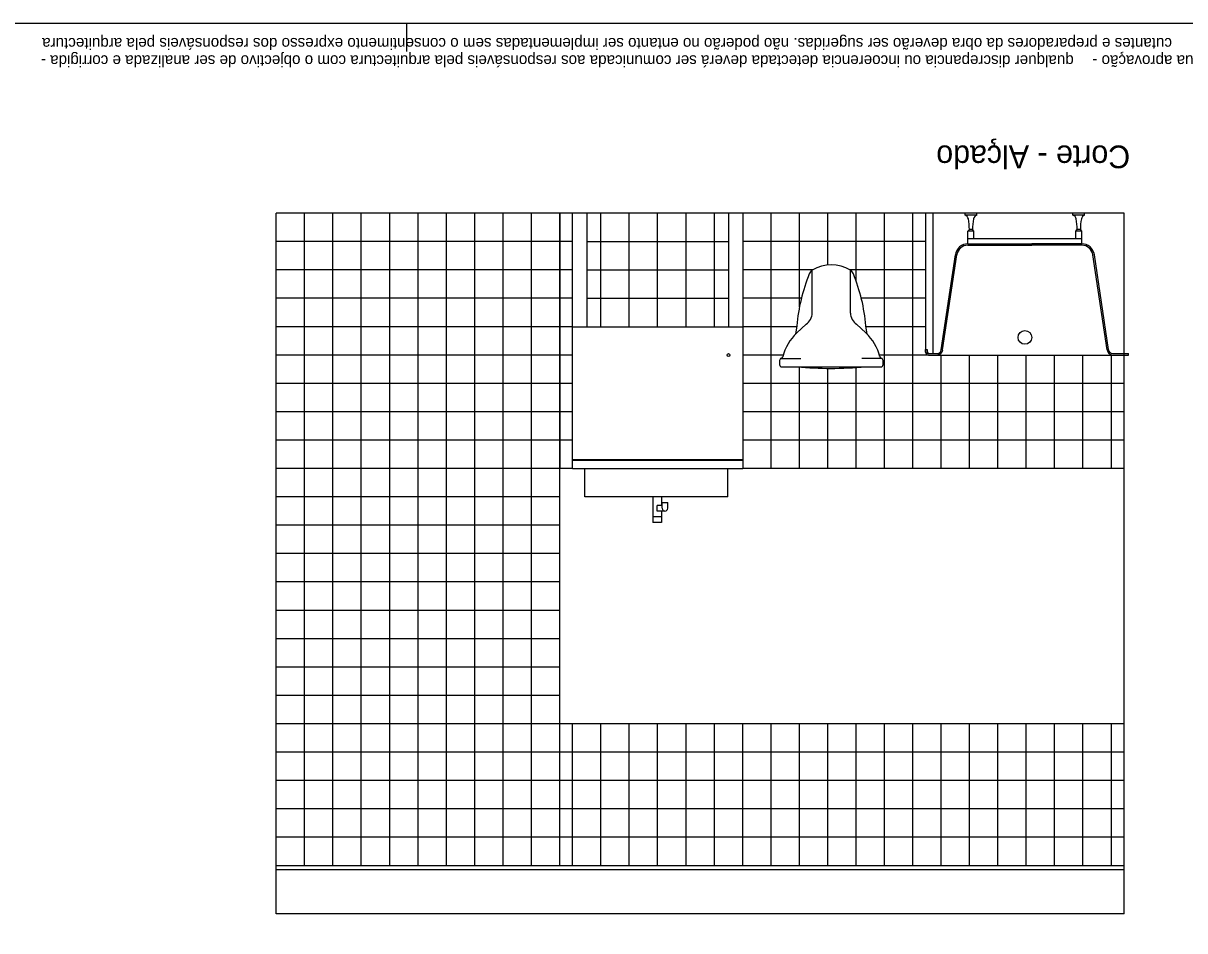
# Model space of a CAD drawing. Extents: x 1302 to 1313.6, y -284.7 to -278.8.
# Drawn here: x 1304.384 to 1308.48, y -281.971 to -278.772 of the extents above; entities that cross this region are included whole.
import ezdxf

# ---------------------------------------------------------------- set-up
doc = ezdxf.new("R2010")
doc.units = 0
for name, color, linetype in [('Level 1', 7, 'Continuous'), ('Level 10', 7, 'Continuous'), ('Level 11', 7, 'Continuous'), ('Level 13', 7, 'Continuous'), ('Level 2', 7, 'Continuous'), ('Level 60', 7, 'Continuous'), ('Level 62', 7, 'Continuous')]:
    doc.layers.add(name, color=color, linetype=linetype)

msp = doc.modelspace()

# ---------------------------------------------------------------- linework, layer by layer
at = {"layer": 'Level 1'}
for p, q in [((1305.2759, -281.9114), (1305.2759, -279.4414)), ((1308.2659, -279.4414), (1305.2759, -279.4414)), ((1307.5659, -279.4414), (1307.5659, -279.9214)), ((1307.5909, -279.4414), (1307.5909, -279.9364)), ((1308.2659, -281.9114), (1308.2659, -279.4414)), ((1307.5659, -279.9214), (1307.5709, -279.9214)), ((1307.5709, -279.9214), (1307.5709, -279.9264)), ((1307.5809, -279.9364), (1307.5909, -279.9364)), ((1308.2659, -281.7414), (1305.2759, -281.7414)), ((1308.2659, -281.7564), (1305.2759, -281.7564)), ((1308.2659, -281.9114), (1305.2759, -281.9114))]:
    msp.add_line(p, q, dxfattribs=at)
msp.add_arc((1307.5809, -279.9264), 0.01, 180, 270, dxfattribs=at)
at = {"layer": 'Level 10'}
for p, q in [((1305.3759, -281.7414), (1305.3759, -279.4414)), ((1305.4759, -281.7414), (1305.4759, -279.4414)), ((1305.5759, -281.7414), (1305.5759, -279.4414)), ((1305.6759, -281.7414), (1305.6759, -279.4414)), ((1305.7759, -281.7414), (1305.7759, -279.4414)), ((1305.8759, -281.7414), (1305.8759, -279.4414)), ((1305.9759, -281.7414), (1305.9759, -279.4414)), ((1306.0759, -281.7414), (1306.0759, -279.4414)), ((1306.1759, -281.7414), (1306.1759, -279.4414)), ((1306.4209, -279.8414), (1306.4209, -279.4414)), ((1306.5209, -279.8414), (1306.5209, -279.4414)), ((1306.6209, -279.8414), (1306.6209, -279.4414)), ((1306.7209, -279.8414), (1306.7209, -279.4414)), ((1306.8209, -279.8414), (1306.8209, -279.4414)), ((1307.0209, -280.3414), (1307.0209, -279.4414)), ((1307.1209, -279.7719), (1307.1209, -279.4414)), ((1307.2209, -279.6238), (1307.2209, -279.4414)), ((1307.3209, -279.6804), (1307.3209, -279.4414)), ((1307.4209, -280.3414), (1307.4209, -279.4414)), ((1307.5209, -280.3414), (1307.5209, -279.4414)), ((1306.2759, -279.5414), (1305.2759, -279.5414)), ((1306.3211, -279.5414), (1306.2759, -279.5414)), ((1306.3711, -279.5414), (1306.8709, -279.5414)), ((1307.5659, -279.5414), (1306.9209, -279.5414)), ((1306.2759, -279.6414), (1305.2759, -279.6414)), ((1306.3211, -279.6414), (1306.2759, -279.6414)), ((1306.3711, -279.6414), (1306.8709, -279.6414)), ((1307.1667, -279.6414), (1306.9209, -279.6414)), ((1307.5659, -279.6414), (1307.3, -279.6414)), ((1306.2759, -279.7414), (1305.2759, -279.7414)), ((1306.3211, -279.7414), (1306.2759, -279.7414)), ((1306.3711, -279.7414), (1306.8709, -279.7414)), ((1307.1276, -279.7414), (1306.9209, -279.7414)), ((1307.5659, -279.7414), (1307.3392, -279.7414)), ((1306.2759, -279.8414), (1305.2759, -279.8414)), ((1306.3211, -279.8414), (1306.2759, -279.8414)), ((1307.1115, -279.8414), (1306.9209, -279.8414)), ((1307.5659, -279.8414), (1307.3555, -279.8414)), ((1306.2759, -279.9414), (1305.2759, -279.9414)), ((1306.3211, -279.9414), (1306.2759, -279.9414)), ((1307.0638, -279.9414), (1306.9209, -279.9414)), ((1307.5759, -279.9414), (1307.403, -279.9414)), ((1307.6209, -280.3414), (1307.6209, -279.9414)), ((1307.7209, -280.3414), (1307.7209, -279.9414)), ((1307.8209, -280.3414), (1307.8209, -279.9414)), ((1307.9209, -280.3414), (1307.9209, -279.9414)), ((1308.0209, -280.3414), (1308.0209, -279.9414)), ((1308.1209, -280.3414), (1308.1209, -279.9414)), ((1308.2209, -280.3414), (1308.2209, -279.9414)), ((1307.1209, -280.3414), (1307.1209, -279.9833)), ((1307.2209, -280.3414), (1307.2209, -279.9883)), ((1307.3209, -280.3414), (1307.3209, -279.9856)), ((1306.2759, -280.0414), (1305.2759, -280.0414)), ((1306.3211, -280.0414), (1306.2759, -280.0414)), ((1308.2659, -280.0414), (1306.9209, -280.0414)), ((1306.2759, -280.1414), (1305.2759, -280.1414)), ((1306.3211, -280.1414), (1306.2759, -280.1414)), ((1308.2659, -280.1414), (1306.9209, -280.1414)), ((1306.2759, -280.2414), (1305.2759, -280.2414)), ((1306.3211, -280.2414), (1306.2759, -280.2414)), ((1308.2659, -280.2414), (1306.9209, -280.2414)), ((1306.2759, -280.3414), (1305.2759, -280.3414)), ((1306.2759, -280.4414), (1305.2759, -280.4414)), ((1306.2759, -280.5414), (1305.2759, -280.5414)), ((1306.2759, -280.6414), (1305.2759, -280.6414)), ((1306.2759, -280.7414), (1305.2759, -280.7414)), ((1306.2759, -280.8414), (1305.2759, -280.8414)), ((1306.2759, -280.9414), (1305.2759, -280.9414)), ((1306.2759, -281.0414), (1305.2759, -281.0414)), ((1306.2759, -281.1414), (1305.2759, -281.1414)), ((1306.2759, -281.2414), (1305.2759, -281.2414)), ((1306.3209, -281.7414), (1306.3209, -281.2414)), ((1306.4209, -281.7414), (1306.4209, -281.2414)), ((1306.5209, -281.7414), (1306.5209, -281.2414)), ((1306.6209, -281.7414), (1306.6209, -281.2414)), ((1306.7209, -281.7414), (1306.7209, -281.2414)), ((1306.8209, -281.7414), (1306.8209, -281.2414)), ((1306.9209, -281.7414), (1306.9209, -281.2414)), ((1307.0209, -281.7414), (1307.0209, -281.2414)), ((1307.1209, -281.7414), (1307.1209, -281.2414)), ((1307.2209, -281.7414), (1307.2209, -281.2414)), ((1307.3209, -281.7414), (1307.3209, -281.2414)), ((1307.4209, -281.7414), (1307.4209, -281.2414)), ((1307.5209, -281.7414), (1307.5209, -281.2414)), ((1307.6209, -281.7414), (1307.6209, -281.2414)), ((1307.7209, -281.7414), (1307.7209, -281.2414)), ((1307.8209, -281.7414), (1307.8209, -281.2414)), ((1307.9209, -281.7414), (1307.9209, -281.2414)), ((1308.0209, -281.7414), (1308.0209, -281.2414)), ((1308.1209, -281.7414), (1308.1209, -281.2414)), ((1308.2209, -281.7414), (1308.2209, -281.2414)), ((1308.2659, -281.3414), (1305.2759, -281.3414)), ((1308.2659, -281.4414), (1305.2759, -281.4414)), ((1308.2659, -281.5414), (1305.2759, -281.5414)), ((1306.8209, -281.7414), (1306.8209, -281.5414)), ((1308.2659, -281.6414), (1305.2759, -281.6414))]:
    msp.add_line(p, q, dxfattribs=at)
at = {"layer": 'Level 11'}
for p, q in [((1307.7464, -279.4413), (1307.7051, -279.4413)), ((1307.7051, -279.448), (1307.7051, -279.4413)), ((1307.7464, -279.448), (1307.7051, -279.448)), ((1307.7464, -279.448), (1307.7464, -279.4413)), ((1308.1266, -279.4413), (1308.0853, -279.4413)), ((1308.0853, -279.448), (1308.0853, -279.4413)), ((1308.1266, -279.448), (1308.0853, -279.448)), ((1308.1266, -279.448), (1308.1266, -279.4413)), ((1307.7153, -279.5049), (1307.7202, -279.4989)), ((1307.7363, -279.5049), (1307.7153, -279.5049)), ((1307.7153, -279.5494), (1307.7153, -279.5049)), ((1307.7314, -279.4989), (1307.7202, -279.4989)), ((1307.7363, -279.5049), (1307.7314, -279.4989)), ((1307.7363, -279.5313), (1307.7363, -279.5049)), ((1308.0955, -279.5049), (1308.1004, -279.4989)), ((1308.1165, -279.5049), (1308.0955, -279.5049)), ((1308.0955, -279.5313), (1308.0955, -279.5049)), ((1308.1116, -279.4989), (1308.1004, -279.4989)), ((1308.1165, -279.5049), (1308.1116, -279.4989)), ((1308.1165, -279.5313), (1308.1165, -279.5049)), ((1308.1165, -279.5313), (1307.7153, -279.5313)), ((1307.7153, -279.5494), (1307.8917, -279.5494)), ((1307.7153, -279.5544), (1307.8917, -279.5544)), ((1307.8917, -279.5494), (1307.9402, -279.5494)), ((1307.8917, -279.5544), (1307.9402, -279.5544)), ((1308.1165, -279.5494), (1307.9402, -279.5494)), ((1308.1165, -279.5544), (1307.9402, -279.5544)), ((1308.1165, -279.5541), (1308.1165, -279.5313)), ((1307.6209, -279.9236), (1307.6708, -279.5877)), ((1307.626, -279.923), (1307.6758, -279.5885)), ((1308.206, -279.923), (1308.1561, -279.5885)), ((1308.2109, -279.9223), (1308.161, -279.5877)), ((1307.1659, -279.7933), (1307.1659, -279.6419)), ((1307.3009, -279.7933), (1307.3009, -279.6419)), ((1307.1117, -279.8386), (1307.1074, -279.8673)), ((1307.1117, -279.8633), (1307.1445, -279.8331)), ((1307.3551, -279.8633), (1307.3223, -279.8331)), ((1307.3594, -279.8673), (1307.3551, -279.8386)), ((1307.5659, -279.9214), (1307.5709, -279.9214)), ((1307.5659, -279.9314), (1307.5659, -279.9214)), ((1307.5709, -279.9314), (1307.5709, -279.9214)), ((1307.0509, -279.9607), (1307.0509, -279.9753)), ((1307.0567, -279.953), (1307.126, -279.953)), ((1307.4101, -279.953), (1307.3408, -279.953)), ((1307.4159, -279.9753), (1307.4159, -279.9607)), ((1307.5759, -279.9364), (1307.606, -279.9364)), ((1307.5759, -279.9414), (1307.6061, -279.9414)), ((1307.6059, -279.9414), (1308.2259, -279.9414)), ((1308.2259, -279.9364), (1308.2809, -279.9364)), ((1308.2259, -279.9414), (1308.2809, -279.9414)), ((1308.2809, -279.9414), (1308.2809, -279.9364)), ((1306.3646, -280.4414), (1306.3646, -280.3414)), ((1306.8689, -280.4414), (1306.8689, -280.3414)), ((1306.6041, -280.4414), (1306.6041, -280.5314)), ((1306.6341, -280.4414), (1306.6341, -280.4714)), ((1306.6367, -280.4814), (1306.6367, -280.4614)), ((1306.6367, -280.4614), (1306.6567, -280.4614)), ((1306.6567, -280.4814), (1306.6567, -280.4614)), ((1306.6041, -280.4914), (1306.6041, -280.5314)), ((1306.6341, -280.4914), (1306.6341, -280.5314)), ((1306.6341, -280.5114), (1306.6041, -280.5114)), ((1306.6341, -280.5314), (1306.6041, -280.5314))]:
    msp.add_line(p, q, dxfattribs=at)
msp.add_lwpolyline([(1307.0589, -279.9833), (1307.2359, -279.9833), (1307.4079, -279.9833)], dxfattribs=at)
msp.add_circle((1307.9159, -279.8794), 0.0242, dxfattribs=at)
for centre, radius, start, end in [((1307.6988, -279.4651), 0.0182, 10.7191, 69.4889), ((1307.5205, -279.4989), 0.1997, 0, 10.7193), ((1307.9311, -279.4989), 0.1997, 169.2806, 180), ((1307.7528, -279.4651), 0.0182, 110.5106, 169.2809), ((1308.079, -279.4651), 0.0182, 10.7191, 69.4889), ((1307.9007, -279.4989), 0.1997, 0, 10.7193), ((1308.3114, -279.4989), 0.1997, 169.2806, 180), ((1308.1331, -279.4651), 0.0182, 110.5106, 169.2809), ((1307.7153, -279.5944), 0.045, 90, 171.5403), ((1307.7153, -279.5944), 0.04, 89.9998, 171.54), ((1308.1165, -279.5944), 0.045, 8.4821, 90.0003), ((1308.1165, -279.5944), 0.04, 8.4823, 89.9998), ((1307.1864, -279.6686), 0.0336, 127.3751, 156.3615), ((1307.2334, -279.7544), 0.1312, 59.0523, 120.9477), ((1307.2805, -279.6686), 0.0336, 23.6385, 52.6249), ((1307.7354, -279.8908), 0.6258, 157.8783, 175.2216), ((1306.7315, -279.8908), 0.6258, 4.7784, 22.1217), ((1307.1144, -279.7912), 0.0516, 305.6694, 357.6894), ((1307.3524, -279.7912), 0.0516, 182.3106, 234.3306), ((1307.2254, -279.9867), 0.1678, 132.6634, 166.3829), ((1307.2414, -279.9867), 0.1678, 13.6171, 47.3366), ((1307.606, -279.9214), 0.015, 270.0008, 351.5408), ((1307.6061, -279.9214), 0.02, 269.9996, 355.2372), ((1308.2259, -279.9214), 0.02, 184.7638, 270.0005), ((1308.2259, -279.9214), 0.015, 184.7638, 270.0005), ((1307.059, -279.9607), 0.008, 106.0135, 180), ((1307.0546, -279.9453), 0.008, 286.0135, 346.3829), ((1307.4123, -279.9453), 0.008, 193.6171, 253.9865), ((1307.4079, -279.9607), 0.008, 0, 73.9865), ((1307.5759, -279.9314), 0.01, 179.9992, 270.0012), ((1307.5759, -279.9314), 0.005, 180.0041, 270.0002), ((1307.059, -279.9753), 0.008, 180, 270), ((1307.241, -278.4128), 1.5757, 265.3469, 269.6323), ((1307.2268, -278.4286), 1.5598, 270.1485, 274.6645), ((1307.4079, -279.9753), 0.008, 270, 0), ((1306.6467, -280.4814), 0.01, 180, 0)]:
    msp.add_arc(centre, radius, start, end, dxfattribs=at)
at = {"layer": 'Level 13'}
for p, q in [((1306.2759, -279.4414), (1306.2759, -280.3414)), ((1306.3211, -280.3414), (1306.3211, -279.4414)), ((1306.3711, -279.4414), (1306.3711, -279.8414)), ((1306.8709, -279.4414), (1306.8709, -279.8414)), ((1306.9209, -279.4414), (1306.9209, -280.3414)), ((1306.3211, -279.8414), (1306.9209, -279.8414)), ((1306.3211, -280.3094), (1306.9209, -280.3094)), ((1306.3211, -280.3114), (1306.9209, -280.3114)), ((1306.3211, -280.3414), (1306.9209, -280.3414)), ((1306.8689, -280.4414), (1306.3646, -280.4414))]:
    msp.add_line(p, q, dxfattribs=at)
msp.add_circle((1306.8709, -279.9414), 0.005, dxfattribs=at)
at = {"layer": 'Level 2'}
for p, q in [((1306.2759, -281.7414), (1306.2759, -279.4414)), ((1306.3211, -280.3414), (1306.2759, -280.3414)), ((1308.2659, -280.3414), (1306.9209, -280.3414)), ((1306.6191, -280.4914), (1306.6191, -280.4714)), ((1306.6367, -280.4714), (1306.6191, -280.4714)), ((1306.6467, -280.4914), (1306.6191, -280.4914)), ((1308.2659, -281.2414), (1306.2759, -281.2414))]:
    msp.add_line(p, q, dxfattribs=at)
at = {"layer": 'Level 62'}
msp.add_line((1305.7367, -278.8718), (1305.7367, -278.7718), dxfattribs=at)
msp.add_lwpolyline([(1313.6363, -278.7718), (1313.6363, -284.7118), (1302.0367, -284.7118), (1302.0367, -278.7718)], close=True, dxfattribs=at)

# ---------------------------------------------------------------- texts
at = {"layer": 'Level 60'}
msp.add_text('Corte - Alçado', height=0.08, rotation=180, dxfattribs=at).set_placement((1308.2873, -279.2027))
at = {"layer": 'Level 62'}
for s, height, p in [('cutantes e preparadores da obra deverão ser sugeridas. não poderão no entanto ser implementadas sem o consentimento expresso dos responsáveis pela arquitectura', 0.0399996, (1308.4347, -278.8238)), ('qualquer discrepancia ou incoerencia detectada deverá ser comunicada aos responsáveis pela arquitectura com o objectivo de ser analizada e corrigida -', 0.0399996, (1308.0881, -278.8848)), ('os desenhos de preparação de obra deverão ser fornecidos ao projectista para sua aprovação -', 0.04, (1310.4255, -278.8848))]:
    msp.add_text(s, height=height, rotation=180, dxfattribs=at).set_placement(p)

doc.saveas('drawing.dxf')
